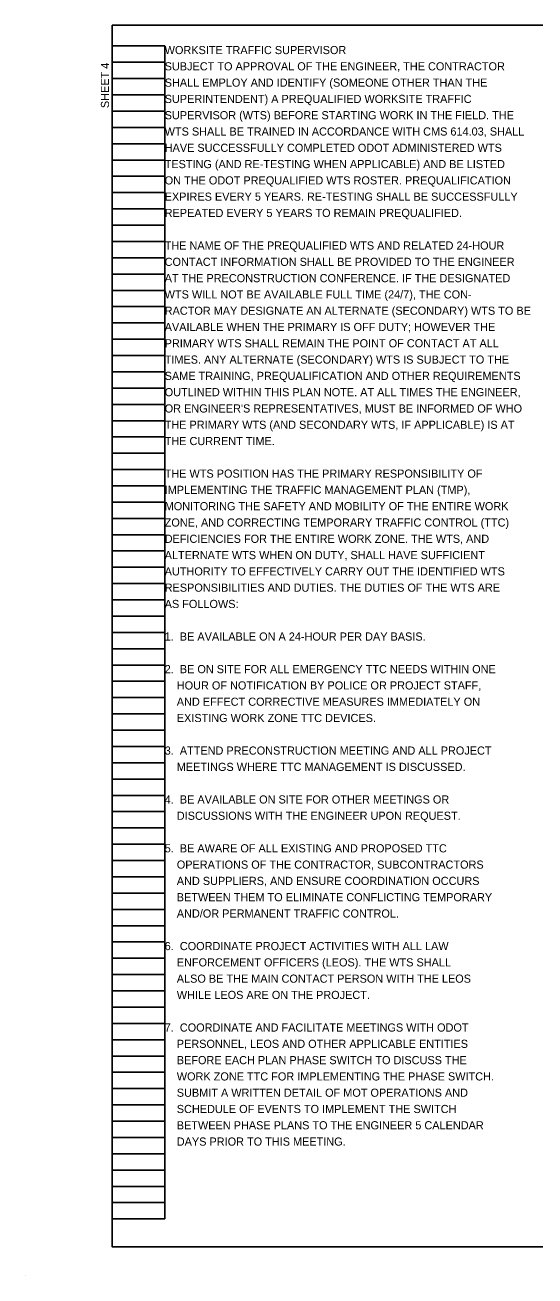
# Model space of a CAD drawing. Extents: x 1820207 to 1820557, y 740216 to 740315.
# Drawn here: x 1820331.58 to 1820340.34, y 740254.24 to 740275.74 of the extents above; entities that cross this region are included whole.
import ezdxf

# ---------------------------------------------------------------- set-up
doc = ezdxf.new("R2010")
doc.units = 0
for name, color, linetype in [('SC_Scratch1', 7, 'Continuous'), ('SC_Scratch2', 7, 'Continuous'), ('SH_Text', 7, 'Continuous')]:
    doc.layers.add(name, color=color, linetype=linetype)

msp = doc.modelspace()

# ---------------------------------------------------------------- linework, layer by layer
at = {"layer": 'SC_Scratch1'}
for p, q in [((1820333.077, 740255.222), (1820333.077, 740275.382)), ((1820333.077, 740275.382), (1820333.977, 740275.382)), ((1820333.977, 740255.222), (1820333.977, 740275.382)), ((1820333.077, 740275.102), (1820333.977, 740275.102)), ((1820333.077, 740274.822), (1820333.977, 740274.822)), ((1820333.077, 740274.542), (1820333.977, 740274.542)), ((1820333.077, 740274.262), (1820333.977, 740274.262)), ((1820333.077, 740273.982), (1820333.977, 740273.982)), ((1820333.077, 740273.702), (1820333.977, 740273.702)), ((1820333.077, 740273.422), (1820333.977, 740273.422)), ((1820333.077, 740273.142), (1820333.977, 740273.142)), ((1820333.077, 740272.862), (1820333.977, 740272.862)), ((1820333.077, 740272.582), (1820333.977, 740272.582)), ((1820333.077, 740272.302), (1820333.977, 740272.302)), ((1820333.077, 740272.022), (1820333.977, 740272.022)), ((1820333.077, 740271.742), (1820333.977, 740271.742)), ((1820333.077, 740271.462), (1820333.977, 740271.462)), ((1820333.077, 740271.182), (1820333.977, 740271.182)), ((1820333.077, 740270.902), (1820333.977, 740270.902)), ((1820333.077, 740270.622), (1820333.977, 740270.622)), ((1820333.077, 740270.342), (1820333.977, 740270.342)), ((1820333.077, 740270.062), (1820333.977, 740270.062)), ((1820333.077, 740269.782), (1820333.977, 740269.782)), ((1820333.077, 740269.502), (1820333.977, 740269.502)), ((1820333.077, 740269.222), (1820333.977, 740269.222)), ((1820333.077, 740268.942), (1820333.977, 740268.942)), ((1820333.077, 740268.662), (1820333.977, 740268.662)), ((1820333.077, 740268.382), (1820333.977, 740268.382)), ((1820333.077, 740268.102), (1820333.977, 740268.102)), ((1820333.077, 740267.822), (1820333.977, 740267.822)), ((1820333.077, 740267.542), (1820333.977, 740267.542)), ((1820333.077, 740267.262), (1820333.977, 740267.262)), ((1820333.077, 740266.982), (1820333.977, 740266.982)), ((1820333.077, 740266.702), (1820333.977, 740266.702)), ((1820333.077, 740266.422), (1820333.977, 740266.422)), ((1820333.077, 740266.142), (1820333.977, 740266.142)), ((1820333.077, 740265.862), (1820333.977, 740265.862)), ((1820333.077, 740265.582), (1820333.977, 740265.582)), ((1820333.077, 740265.302), (1820333.977, 740265.302)), ((1820333.077, 740265.022), (1820333.977, 740265.022)), ((1820333.077, 740264.742), (1820333.977, 740264.742)), ((1820333.077, 740264.462), (1820333.977, 740264.462)), ((1820333.077, 740264.182), (1820333.977, 740264.182)), ((1820333.077, 740263.902), (1820333.977, 740263.902)), ((1820333.077, 740263.622), (1820333.977, 740263.622)), ((1820333.077, 740263.342), (1820333.977, 740263.342)), ((1820333.077, 740263.062), (1820333.977, 740263.062)), ((1820333.077, 740262.782), (1820333.977, 740262.782)), ((1820333.077, 740262.502), (1820333.977, 740262.502)), ((1820333.077, 740262.222), (1820333.977, 740262.222)), ((1820333.077, 740261.942), (1820333.977, 740261.942)), ((1820333.077, 740261.662), (1820333.977, 740261.662)), ((1820333.077, 740261.382), (1820333.977, 740261.382)), ((1820333.077, 740261.102), (1820333.977, 740261.102)), ((1820333.077, 740260.822), (1820333.977, 740260.822)), ((1820333.077, 740260.542), (1820333.977, 740260.542)), ((1820333.077, 740260.262), (1820333.977, 740260.262)), ((1820333.077, 740259.982), (1820333.977, 740259.982)), ((1820333.077, 740259.702), (1820333.977, 740259.702)), ((1820333.077, 740259.422), (1820333.977, 740259.422)), ((1820333.077, 740259.142), (1820333.977, 740259.142)), ((1820333.077, 740258.862), (1820333.977, 740258.862)), ((1820333.077, 740258.582), (1820333.977, 740258.582)), ((1820333.077, 740258.302), (1820333.977, 740258.302)), ((1820333.077, 740258.022), (1820333.977, 740258.022)), ((1820333.077, 740257.742), (1820333.977, 740257.742)), ((1820333.077, 740257.462), (1820333.977, 740257.462)), ((1820333.077, 740257.182), (1820333.977, 740257.182)), ((1820333.077, 740256.902), (1820333.977, 740256.902)), ((1820333.077, 740256.622), (1820333.977, 740256.622)), ((1820333.077, 740256.342), (1820333.977, 740256.342)), ((1820333.077, 740256.062), (1820333.977, 740256.062)), ((1820333.077, 740255.782), (1820333.977, 740255.782)), ((1820333.077, 740255.502), (1820333.977, 740255.502)), ((1820333.077, 740255.222), (1820333.977, 740255.222)), ((1820331.577, 740254.242), (1820331.577, 740254.242))]:
    msp.add_line(p, q, dxfattribs=at)
at = {"layer": 'SC_Scratch2'}
msp.add_lwpolyline([(1820333.077, 740275.742), (1820363.577, 740275.742), (1820363.577, 740254.742), (1820333.077, 740254.742)], close=True, dxfattribs=at)

# ---------------------------------------------------------------- texts
at = {"layer": 'SH_Text'}
for s, p in [('WORKSITE TRAFFIC SUPERVISOR', (1820333.977, 740275.242)), ('SUBJECT TO APPROVAL OF THE ENGINEER, THE CONTRACTOR', (1820333.977, 740274.962)), ('SHALL EMPLOY AND IDENTIFY (SOMEONE OTHER THAN THE', (1820333.977, 740274.682)), ('SUPERINTENDENT) A PREQUALIFIED WORKSITE TRAFFIC', (1820333.977, 740274.402)), ('SUPERVISOR (WTS) BEFORE STARTING WORK IN THE FIELD. THE', (1820333.977, 740274.122)), ('WTS SHALL BE TRAINED IN ACCORDANCE WITH CMS 614.03, SHALL', (1820333.977, 740273.842)), ('HAVE SUCCESSFULLY COMPLETED ODOT ADMINISTERED WTS', (1820333.977, 740273.562)), ('TESTING (AND RE-TESTING WHEN APPLICABLE) AND BE LISTED', (1820333.977, 740273.282)), ('ON THE ODOT PREQUALIFIED WTS ROSTER. PREQUALIFICATION', (1820333.977, 740273.002)), ('EXPIRES EVERY 5 YEARS. RE-TESTING SHALL BE SUCCESSFULLY', (1820333.977, 740272.722)), ('REPEATED EVERY 5 YEARS TO REMAIN PREQUALIFIED.', (1820333.977, 740272.442)), ('THE NAME OF THE PREQUALIFIED WTS AND RELATED 24-HOUR', (1820333.977, 740271.882)), ('CONTACT INFORMATION SHALL BE PROVIDED TO THE ENGINEER', (1820333.977, 740271.602)), ('AT THE PRECONSTRUCTION CONFERENCE. IF THE DESIGNATED', (1820333.977, 740271.322)), ('WTS WILL NOT BE AVAILABLE FULL TIME (24/7), THE CON-', (1820333.977, 740271.042)), ('RACTOR MAY DESIGNATE AN ALTERNATE (SECONDARY) WTS TO BE', (1820333.977, 740270.762)), ('AVAILABLE WHEN THE PRIMARY IS OFF DUTY; HOWEVER THE', (1820333.977, 740270.482)), ('PRIMARY WTS SHALL REMAIN THE POINT OF CONTACT AT ALL', (1820333.977, 740270.202)), ('TIMES. ANY ALTERNATE (SECONDARY) WTS IS SUBJECT TO THE', (1820333.977, 740269.922)), ('SAME TRAINING, PREQUALIFICATION AND OTHER REQUIREMENTS', (1820333.977, 740269.642)), ('OUTLINED WITHIN THIS PLAN NOTE. AT ALL TIMES THE ENGINEER,', (1820333.977, 740269.362)), ("OR ENGINEER'S REPRESENTATIVES, MUST BE INFORMED OF WHO", (1820333.977, 740269.082)), ('THE PRIMARY WTS (AND SECONDARY WTS, IF APPLICABLE) IS AT', (1820333.977, 740268.802)), ('THE CURRENT TIME.', (1820333.977, 740268.522)), ('THE WTS POSITION HAS THE PRIMARY RESPONSIBILITY OF', (1820333.977, 740267.962)), ('IMPLEMENTING THE TRAFFIC MANAGEMENT PLAN (TMP),', (1820333.977, 740267.682)), ('MONITORING THE SAFETY AND MOBILITY OF THE ENTIRE WORK', (1820333.977, 740267.402)), ('ZONE, AND CORRECTING TEMPORARY TRAFFIC CONTROL (TTC)', (1820333.977, 740267.122)), ('DEFICIENCIES FOR THE ENTIRE WORK ZONE. THE WTS, AND', (1820333.977, 740266.842)), ('ALTERNATE WTS WHEN ON DUTY, SHALL HAVE SUFFICIENT', (1820333.977, 740266.562)), ('AUTHORITY TO EFFECTIVELY CARRY OUT THE IDENTIFIED WTS', (1820333.977, 740266.282)), ('RESPONSIBILITIES AND DUTIES. THE DUTIES OF THE WTS ARE', (1820333.977, 740266.002)), ('AS FOLLOWS:', (1820333.977, 740265.722)), ('1.  BE AVAILABLE ON A 24-HOUR PER DAY BASIS.', (1820333.977, 740265.162)), ('2.  BE ON SITE FOR ALL EMERGENCY TTC NEEDS WITHIN ONE', (1820333.977, 740264.602)), ('    HOUR OF NOTIFICATION BY POLICE OR PROJECT STAFF,', (1820333.977, 740264.322)), ('    AND EFFECT CORRECTIVE MEASURES IMMEDIATELY ON', (1820333.977, 740264.042)), ('    EXISTING WORK ZONE TTC DEVICES.', (1820333.977, 740263.762)), ('3.  ATTEND PRECONSTRUCTION MEETING AND ALL PROJECT', (1820333.977, 740263.202)), ('    MEETINGS WHERE TTC MANAGEMENT IS DISCUSSED.', (1820333.977, 740262.922)), ('4.  BE AVAILABLE ON SITE FOR OTHER MEETINGS OR', (1820333.977, 740262.362)), ('    DISCUSSIONS WITH THE ENGINEER UPON REQUEST.', (1820333.977, 740262.082)), ('5.  BE AWARE OF ALL EXISTING AND PROPOSED TTC', (1820333.977, 740261.522)), ('    OPERATIONS OF THE CONTRACTOR, SUBCONTRACTORS', (1820333.977, 740261.242)), ('    AND SUPPLIERS, AND ENSURE COORDINATION OCCURS', (1820333.977, 740260.962)), ('    BETWEEN THEM TO ELIMINATE CONFLICTING TEMPORARY', (1820333.977, 740260.682)), ('    AND/OR PERMANENT TRAFFIC CONTROL.', (1820333.977, 740260.402)), ('6.  COORDINATE PROJECT ACTIVITIES WITH ALL LAW', (1820333.977, 740259.842)), ('    ENFORCEMENT OFFICERS (LEOS). THE WTS SHALL', (1820333.977, 740259.562)), ('    ALSO BE THE MAIN CONTACT PERSON WITH THE LEOS', (1820333.977, 740259.282)), ('    WHILE LEOS ARE ON THE PROJECT.', (1820333.977, 740259.002)), ('7.  COORDINATE AND FACILITATE MEETINGS WITH ODOT', (1820333.977, 740258.442)), ('    PERSONNEL, LEOS AND OTHER APPLICABLE ENTITIES', (1820333.977, 740258.162)), ('    BEFORE EACH PLAN PHASE SWITCH TO DISCUSS THE', (1820333.977, 740257.882)), ('    WORK ZONE TTC FOR IMPLEMENTING THE PHASE SWITCH.', (1820333.977, 740257.602)), ('    SUBMIT A WRITTEN DETAIL OF MOT OPERATIONS AND', (1820333.977, 740257.322)), ('    SCHEDULE OF EVENTS TO IMPLEMENT THE SWITCH', (1820333.977, 740257.042)), ('    BETWEEN PHASE PLANS TO THE ENGINEER 5 CALENDAR', (1820333.977, 740256.762)), ('    DAYS PRIOR TO THIS MEETING.', (1820333.977, 740256.482))]:
    msp.add_text(s, height=0.14, dxfattribs=at).set_placement(p)
msp.add_text('SHEET 4', height=0.14, rotation=90, dxfattribs=at).set_placement((1820333.021, 740274.314))

doc.saveas('drawing.dxf')
